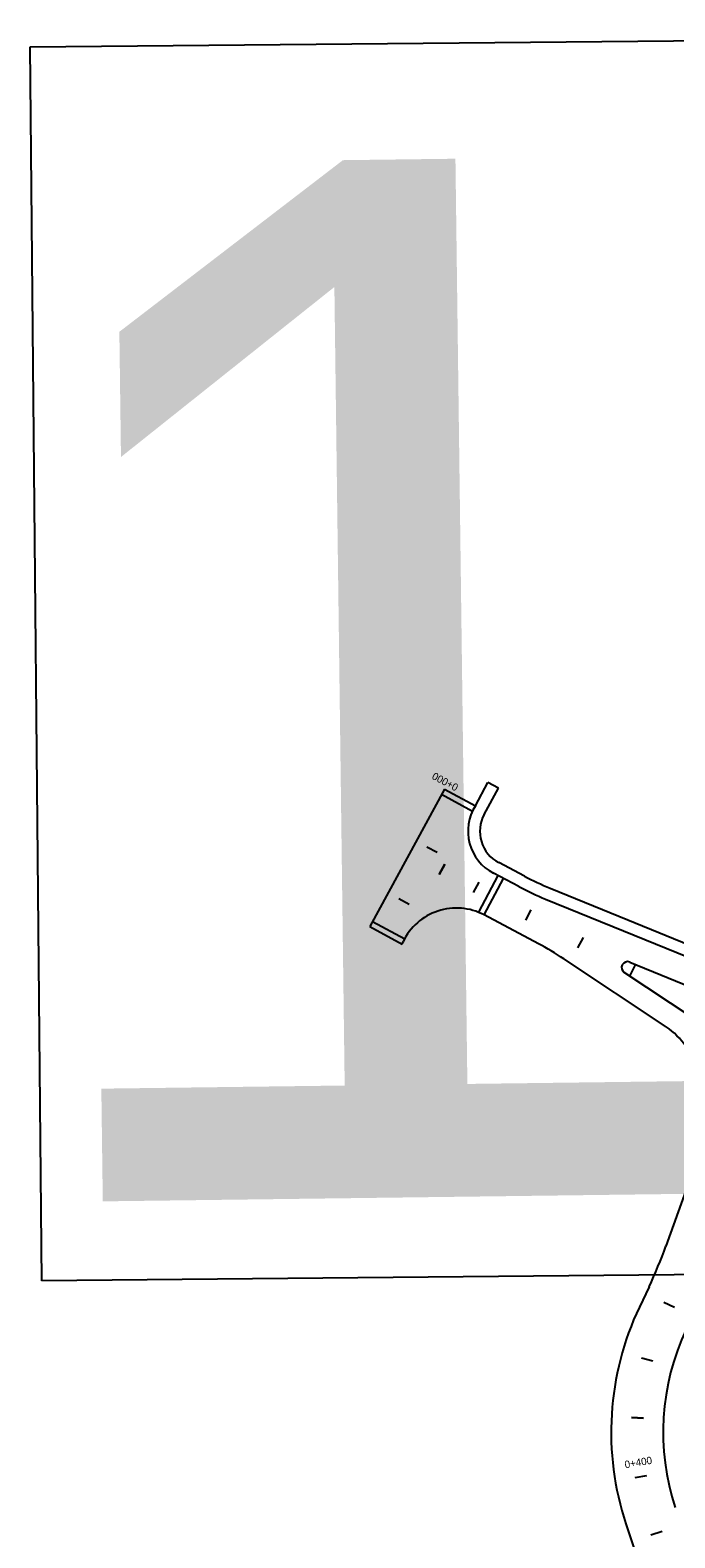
# Model space of a CAD drawing. Extents: x 6503541 to 6503743, y 5888004 to 5888145.
# Drawn here: x 6503687.04 to 6503689.66, y 5888093.5 to 5888099.63 of the extents above; entities that cross this region are included whole.
import ezdxf

# ---------------------------------------------------------------- set-up
doc = ezdxf.new("R2010")
doc.units = 0
doc.layers.add('12', color=7, linetype='Continuous')
doc.layers.add('tabela', color=7, linetype='Continuous')

msp = doc.modelspace()

# ---------------------------------------------------------------- linework, layer by layer
at = {"layer": '12'}
for p, q in [((6503688.8511, 5888096.4773), (6503688.9024, 5888096.5724)), ((6503688.9446, 5888096.5496), (6503688.9024, 5888096.5724)), ((6503688.7252, 5888096.5456), (6503688.4218, 5888095.9864)), ((6503688.7137, 5888096.5245), (6503688.8397, 5888096.4562)), ((6503688.7252, 5888096.5456), (6503688.8511, 5888096.4773)), ((6503688.8868, 5888096.4423), (6503688.9446, 5888096.5496)), ((6503689.0509, 5888096.1913), (6503688.9461, 5888096.2468)), ((6503688.8651, 5888096.045), (6503688.9439, 5888096.1937)), ((6503688.8863, 5888096.0338), (6503688.9651, 5888096.1824)), ((6503689.0285, 5888096.1488), (6503688.9245, 5888096.2039)), ((6503689.1551, 5888096.1426), (6503689.4715, 5888096.0134)), ((6503689.137, 5888096.0981), (6503689.4533, 5888095.969)), ((6503688.4331, 5888096.0073), (6503688.5642, 5888095.9365)), ((6503689.1077, 5888095.9165), (6503688.8863, 5888096.0338)), ((6503689.4715, 5888096.0134), (6503689.7539, 5888095.8982)), ((6503688.4217, 5888095.9861), (6503688.5528, 5888095.9154)), ((6503689.4533, 5888095.969), (6503689.7571, 5888095.845)), ((6503688.5528, 5888095.9154), (6503688.5573, 5888095.9248)), ((6503689.6273, 5888095.5781), (6503689.2104, 5888095.8553)), ((6503689.4791, 5888095.8418), (6503689.7906, 5888095.7147)), ((6503689.7369, 5888095.6133), (6503689.4568, 5888095.7996)), ((6503689.7697, 5888095.0867), (6503689.6263, 5888094.6865)), ((6503689.5575, 5888094.5209), (6503689.5182, 5888094.4384)), ((6503689.4638, 5888093.556), (6503689.6161, 5888093.097))]:
    msp.add_line(p, q, dxfattribs=at)
for points in [[(6503688.6533, 5888096.3114), (6503688.6956, 5888096.2887)], [(6503688.704, 5888096.1983), (6503688.7264, 5888096.2407)], [(6503688.7264, 5888096.2407), (6503688.704, 5888096.1983)], [(6503688.8652, 5888096.1672), (6503688.8427, 5888096.1248)], [(6503688.5398, 5888096.0999), (6503688.5821, 5888096.0772)], [(6503689.0773, 5888096.0548), (6503689.0548, 5888096.0124)], [(6503689.2893, 5888095.9425), (6503689.2669, 5888095.9001)], [(6503689.5014, 5888095.8301), (6503689.479, 5888095.7877)], [(6503689.6607, 5888094.4363), (6503689.6174, 5888094.4569)], [(6503689.5731, 5888094.2176), (6503689.5269, 5888094.2307)], [(6503689.4866, 5888093.9895), (6503689.5346, 5888093.9869)], [(6503689.5346, 5888093.9866), (6503689.4866, 5888093.9892)], [(6503689.5006, 5888093.7448), (6503689.5479, 5888093.7528)], [(6503689.6105, 5888093.5252), (6503689.5649, 5888093.5101)]]:
    msp.add_lwpolyline(points, dxfattribs=at)
for centre, radius, start, end in [((6503689.0134, 5888096.3743), 0.1922, 147.62773, 242.42969), ((6503689.0136, 5888096.374), 0.144, 151.68124, 242.07885), ((6503689.5904, 5888097.2092), 1.152, 242.07885, 247.79978), ((6503689.5904, 5888097.2092), 1.2, 242.07885, 247.79978), ((6503688.774, 5888095.8217), 0.24, 62.08918, 154.54305), ((6503688.546, 5888094.8561), 1.2, 56.37859, 62.08918), ((6503689.47, 5888095.8196), 0.024, 67.79978, 236.37859), ((6503689.4679, 5888095.3383), 0.288, 11.46739, 56.37859), ((6503687.9318, 5888095.2937), 1.8, 334.57508, 340.28568), ((6503690.589, 5888093.9294), 1.1856, 154.57508, 198.36012), ((6503690.589, 5888093.9294), 0.9744, 154.57508, 198.36012)]:
    msp.add_arc(centre, radius, start, end, dxfattribs=at)
at = {"layer": 'tabela'}
for p, q in [((6503687.0403, 5888099.5657), (6503694.2758, 5888099.6333)), ((6503687.0403, 5888099.5657), (6503694.2758, 5888099.6333)), ((6503687.0872, 5888094.5456), (6503687.0403, 5888099.5657)), ((6503687.0872, 5888094.5456), (6503687.0403, 5888099.5657)), ((6503694.3226, 5888094.6132), (6503687.0872, 5888094.5456)), ((6503694.3226, 5888094.6132), (6503687.0872, 5888094.5456))]:
    msp.add_line(p, q, dxfattribs=at)

# ---------------------------------------------------------------- texts
at = {"layer": '12'}
for s, height, rotation, p in [('15', 4.22297, 0.73934, (6503686.9056, 5888094.8628)), ('0+000', 0.03, 151.7807, (6503688.7849, 5888096.5622)), ('0+400', 0.03, 9.62663, (6503689.4608, 5888093.7823))]:
    msp.add_text(s, height=height, rotation=rotation, dxfattribs=at).set_placement(p)

doc.saveas('drawing.dxf')
